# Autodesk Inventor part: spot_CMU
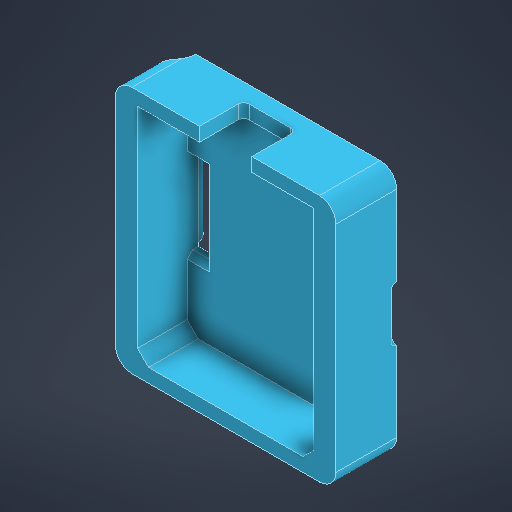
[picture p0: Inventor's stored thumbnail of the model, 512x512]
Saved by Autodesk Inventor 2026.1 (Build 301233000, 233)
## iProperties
Created: 2025-11
Part Number: spot_CMU
Material: Generico
Document SubType Name: Modeling
Designer: Gek
Density: 1 g/cm^3
Appearance: Turchese
Author: Gek
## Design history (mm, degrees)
sketch "Schizzo1"
  geometry: L1 (20, 22.5)-(-20, 22.5); L2 (-20, 22.5)-(-20, -22.5); L3 (-20, -22.5)-(20, -22.5); L4 (20, -22.5)-(20, 22.5); L5 (28, 0)-(-28, 0) reference; L6 (0, -31.5)-(0, 31.5) reference; 1 further point
  constraints: 8 end point, 2 parallel, 1 horizontal, 1 perpendicular, 2 other
  dimensions: "d0" = 40 distance of L1.start L1.end; "d1" = 45 distance of L3.end L1.start
extrude "Estrusione1" new body sketch "Schizzo1" distance "d2" = 11; taper "d3" = 0 deg
sketch "Schizzo2"
  geometry: L1 (-16, -20)-(16, -20); L2 (16, -20)-(16, 20); L3 (16, 20)-(-16, 20); L4 (-16, 20)-(-16, -20); L5 (0, -31.5)-(0, 31.5) reference; L6 (-28, 0)-(28, 0) reference; 1 further point
  constraints: 8 end point, 2 parallel, 1 horizontal, 1 perpendicular, 2 other
  dimensions: "d4" = 32 distance of L1.start L1.end; "d5" = 40 distance of L3.end L1.start
extrude "Estrusione2" cut sketch "Schizzo2" distance "d6" = 9; taper "d7" = 0 deg
sketch "Schizzo3"
  geometry: L1 (-16, 20)-(16, 20) reference; L2 (-20, 22.5)-(20, 22.5) reference; L3 (-4.75, 20)-(4.75, 20); L4 (4.75, 20)-(4.75, 22.5); L5 (4.75, 22.5)-(-4.75, 22.5); L6 (-4.75, 22.5)-(-4.75, 20); L7 (0, -31.5)-(0, 31.5) reference; 3 further points
  constraints: 8 end point, 2 parallel, 2 point on line, 1 horizontal, 1 perpendicular, 1 other
  dimensions: "d8" = 9.5 distance between parallel lines of L4 L6
extrude "Estrusione3" cut sketch "Schizzo3" distance "d9" = 8; taper "d10" = 0 deg
chamfer "Smusso1" distance "d13" = 2; stored, may be unused: second distance "d14" = 2, angle "d15" = 45 deg
sketch "Schizzo4"
  geometry: L1 (40, 0)-(40, 11) reference; C1 r 3.5 at (40, 11); 1 further point
  constraints: 1 centre point
  dimensions: "d16" = 7 diameter of C1
extrude "Estrusione4" join sketch "Schizzo4" stored distance "d17" = 9; taper "d18" = 0 deg
sketch "Schizzo5"
  geometry: C1 r 1 at (40, 11); A1 r 3.5 centre (40, 11) between (40, 7.5) and (36.5, 11) reference; 1 further point
  constraints: 1 centre point, 1 coincident
  dimensions: "d19" = 2 diameter of C1
extrude "Estrusione5" cut sketch "Schizzo5" extent not by distance; stored distance "d20" = 0; taper "d21" = 0 deg
sketch "Schizzo6"
  geometry: C1 r 1 at (40, 11) reference; C2 r 3.6 at (40, 11); 1 further point
  constraints: 1 centre point, 1 coincident
  dimensions: "d22" = 7.2 diameter of C2
extrude "Estrusione6" cut sketch "Schizzo6" distance "d23" = 15; taper "d24" = 0 deg
mirror "Speculare1"
fillet "Raccordo3" dims "d25" = 3
chamfer "Smusso2" distance "d29" = 0.5; stored, may be unused: second distance "d30" = 2, angle "d31" = 45 deg
sketch "Schizzo8"
  geometry: L1 (-16, 18)-(-16, -20) reference; L2 (-16, 7.5)-(-13, 7.5); L3 (-13, 7.5)-(-13, -7.5); L4 (-13, -7.5)-(-16, -7.5); L5 (-16, -7.5)-(-16, 7.5); L6 (-16.5, -7.5)-(-16.4, -7.5) reference; L7 (-16.4, 7.5)-(-16.5, 7.5) reference; 2 further points
  constraints: 8 end point, 2 collinear, 2 parallel, 1 horizontal, 1 perpendicular, 1 point on line
  dimensions: "d35" = 3 distance of L2.start L2.end
extrude "Estrusione8" cut sketch "Schizzo8" distance "d36" = 4.5; taper "d37" = 0 deg
chamfer "Smusso4" distance "d38" = 1; stored, may be unused: second distance "d39" = 2, angle "d40" = 45 deg
fillet "Raccordo4" dims "d41" = 1
fillet "Raccordo5" dims "d42" = 19
fillet "Raccordo6" dims "d43" = 2
sketch "Schizzo9"
  geometry: L1 (17, 11)-(20, 11) reference; C1 r 1 at (20, 11); 1 further point
  constraints: 1 centre point
  dimensions: "d44" = 2 diameter of C1
extrude "Estrusione9" cut sketch "Schizzo9" stored distance "d45" = 10; taper "d46" = 0 deg
fillet "Raccordo7" dims "d47" = 1
node "Solido1"
